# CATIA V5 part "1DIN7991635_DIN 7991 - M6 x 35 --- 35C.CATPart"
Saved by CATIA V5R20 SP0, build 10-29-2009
Part number: 1DIN7991635_DIN 7991 - M6 x 35 --- 35C
Revision: ANY
Definition: UNKNOWN
Nomenclature: 1DIN7991635_DIN 7991 - M6 x 35 --- 35C
Source: Unknown
Bounding box of the stored display mesh (mm): x 0 to 35, y -5.785 to 5.785, z -5.785 to 5.785
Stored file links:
  C:\Users\Utente\Desktop\IO LAVORO\3D X SITO CF\CUMSA\3D files PO\PO 250635\1DIN7991635_DIN 7991 - M6 x 35 --- 35C.CATPart
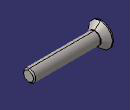
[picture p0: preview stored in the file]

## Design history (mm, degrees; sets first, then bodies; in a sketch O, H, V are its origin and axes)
Body1 "Hex" (main body)
  Solid1: solid without history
